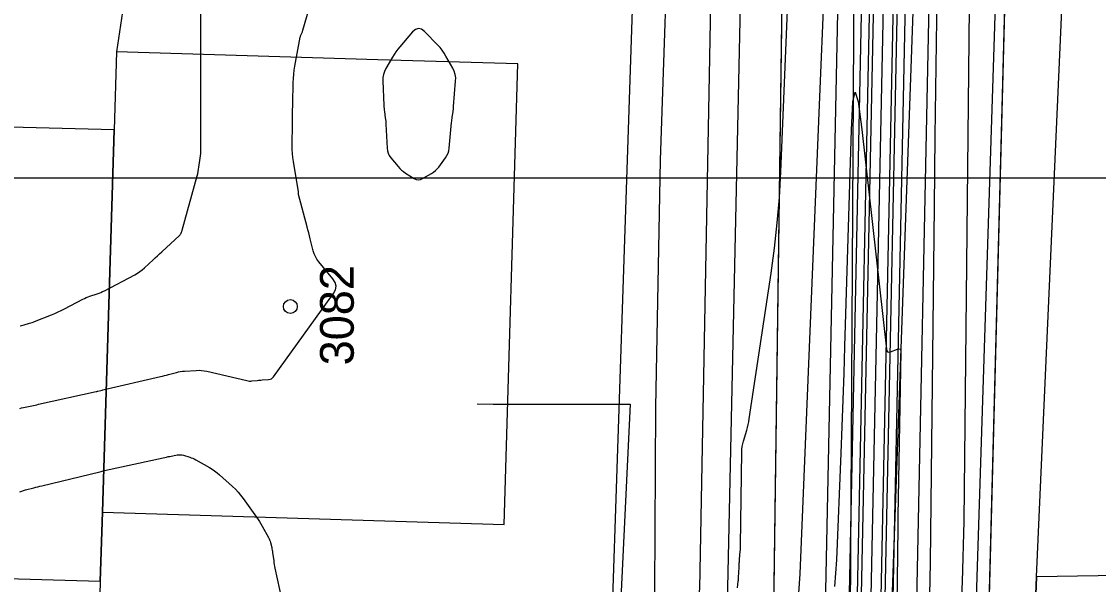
# Model space of a CAD drawing. Extents: x -534410 to -534262, y -1190162 to -1189584.
# Drawn here: x -534345.75 to -534318.59, y -1190119.71 to -1190105.52 of the extents above; entities that cross this region are included whole.
import ezdxf

# ---------------------------------------------------------------- set-up
doc = ezdxf.new("R2010")
doc.units = 0
for name, color, linetype in [('07_ELEKTRO', 7, 'Continuous'), ('30', 7, 'Continuous'), ('31', 7, 'Continuous'), ('_linie', 7, 'Continuous'), ('_N_osa', 7, 'Continuous'), ('_N_tenká', 7, 'Continuous'), ('_N_tenká_velmi', 7, 'Continuous'), ('_přístup', 7, 'Continuous'), ('_rámeček', 7, 'Continuous'), ('_tenka', 7, 'Continuous'), ('Default', 7, 'Continuous'), ('Hranice parcel', 7, 'Continuous'), ('Parcelní čísla', 7, 'Continuous'), ('Polygon budovy', 7, 'Continuous'), ('Vrstva 1', 7, 'Continuous'), ('Značky budov', 7, 'Continuous')]:
    doc.layers.add(name, color=color, linetype=linetype)

msp = doc.modelspace()

# ---------------------------------------------------------------- linework, layer by layer
at = {"layer": '07_ELEKTRO'}
msp.add_lwpolyline([(-534340.501, -1190135.539), (-534331.273, -1190133.27), (-534330.81, -1190133.08), (-534330.32, -1190132.66), (-534330.24, -1190132.17), (-534330.24, -1190130.93), (-534330.14, -1190126.19), (-534329.99, -1190122.81), (-534329.79, -1190121.43), (-534329.75, -1190115.24), (-534329.64, -1190109.01), (-534329.39, -1190101.86), (-534329.4, -1190094.43), (-534329.31, -1190087.46), (-534329.03, -1190079.95)], dxfattribs=at)
at = {"layer": '30'}
for points in [[(-534345.785, -1190115.274), (-534345.743, -1190115.262), (-534345.7, -1190115.252), (-534345.657, -1190115.243), (-534345.485, -1190115.206), (-534345.442, -1190115.197), (-534345.399, -1190115.188), (-534345.357, -1190115.179), (-534345.314, -1190115.169), (-534343.868, -1190114.85), (-534343.855, -1190114.847), (-534343.843, -1190114.844), (-534343.83, -1190114.841), (-534343.818, -1190114.838), (-534343.743, -1190114.818), (-534343.712, -1190114.81), (-534343.698, -1190114.807), (-534342.24, -1190114.471), (-534342.19, -1190114.459), (-534342.14, -1190114.447), (-534342.09, -1190114.434), (-534342.04, -1190114.42), (-534341.842, -1190114.365), (-534341.792, -1190114.352), (-534341.742, -1190114.342), (-534341.691, -1190114.335), (-534341.64, -1190114.331), (-534341.339, -1190114.313), (-534341.271, -1190114.311), (-534341.205, -1190114.315), (-534341.138, -1190114.323), (-534341.072, -1190114.336), (-534340.063, -1190114.572), (-534340.032, -1190114.578), (-534340, -1190114.582), (-534339.968, -1190114.582), (-534339.936, -1190114.58), (-534339.807, -1190114.566), (-534339.775, -1190114.562), (-534339.743, -1190114.559), (-534339.711, -1190114.557), (-534339.678, -1190114.555), (-534339.515, -1190114.545), (-534339.479, -1190114.539), (-534339.447, -1190114.526), (-534339.418, -1190114.506), (-534339.394, -1190114.478), (-534337.882, -1190112.378), (-534337.831, -1190112.282), (-534337.816, -1190112.187), (-534337.838, -1190112.094), (-534337.895, -1190112.002), (-534338.252, -1190111.575), (-534338.298, -1190111.512), (-534338.337, -1190111.446), (-534338.368, -1190111.376), (-534338.39, -1190111.302), (-534338.466, -1190110.997), (-534338.485, -1190110.921), (-534338.504, -1190110.845), (-534338.524, -1190110.769), (-534338.544, -1190110.693), (-534338.762, -1190109.876), (-534338.763, -1190109.871), (-534338.764, -1190109.866), (-534338.764, -1190109.861), (-534338.765, -1190109.856), (-534338.764, -1190109.834), (-534338.764, -1190109.829), (-534338.764, -1190109.824), (-534338.765, -1190109.819), (-534338.765, -1190109.813), (-534338.893, -1190109.05), (-534338.908, -1190108.947), (-534338.918, -1190108.844), (-534338.923, -1190108.74), (-534338.923, -1190108.636), (-534338.911, -1190108.094), (-534338.911, -1190108.053), (-534338.91, -1190108.011), (-534338.91, -1190107.969), (-534338.91, -1190107.928), (-534338.91, -1190107.761), (-534338.91, -1190107.72), (-534338.909, -1190107.678), (-534338.909, -1190107.636), (-534338.908, -1190107.595), (-534338.896, -1190107.053), (-534338.891, -1190106.949), (-534338.883, -1190106.845), (-534338.87, -1190106.742), (-534338.853, -1190106.64), (-534338.718, -1190105.907), (-534338.714, -1190105.891), (-534338.71, -1190105.876), (-534338.705, -1190105.862), (-534338.699, -1190105.847), (-534338.673, -1190105.79), (-534338.666, -1190105.775), (-534338.661, -1190105.761), (-534338.656, -1190105.746), (-534338.651, -1190105.731), (-534338.432, -1190104.986)], [(-534328.533, -1190137.603), (-534328.812, -1190134.889), (-534328.812, -1190134.881), (-534328.812, -1190134.873), (-534328.811, -1190134.866), (-534328.81, -1190134.858), (-534328.803, -1190134.826), (-534328.801, -1190134.819), (-534328.799, -1190134.811), (-534328.798, -1190134.803), (-534328.796, -1190134.795), (-534327.299, -1190125.114), (-534327.218, -1190124.637), (-534327.125, -1190124.162), (-534327.02, -1190123.691), (-534326.902, -1190123.222), (-534326.404, -1190121.352), (-534326.293, -1190120.882), (-534326.208, -1190120.408), (-534326.148, -1190119.931), (-534326.115, -1190119.449), (-534325.609, -1190107.213), (-534325.521, -1190105.013)], [(-534322.669, -1190104.87), (-534322.696, -1190106.64), (-534322.719, -1190108.41), (-534322.739, -1190110.18), (-534322.834, -1190119.161), (-534322.854, -1190119.98), (-534322.897, -1190120.797), (-534322.962, -1190121.613), (-534323.05, -1190122.427), (-534323.447, -1190125.682), (-534323.548, -1190126.496), (-534323.651, -1190127.309), (-534323.757, -1190128.122), (-534323.865, -1190128.934), (-534324.553, -1190134.018), (-534324.555, -1190134.032), (-534324.557, -1190134.046), (-534324.563, -1190134.074), (-534324.564, -1190134.082), (-534324.565, -1190134.089), (-534324.565, -1190134.096), (-534324.566, -1190134.103), (-534324.575, -1190136.191)]]:
    msp.add_lwpolyline(points, dxfattribs=at)
at = {"layer": '31'}
for points in [[(-534327.696, -1190119.802), (-534327.675, -1190119.627), (-534327.673, -1190119.603), (-534327.671, -1190119.579), (-534327.669, -1190119.556), (-534327.668, -1190119.532), (-534327.663, -1190119.411), (-534327.663, -1190119.4), (-534327.662, -1190119.389), (-534327.661, -1190119.378), (-534327.66, -1190119.367), (-534327.657, -1190119.323), (-534327.656, -1190119.313), (-534327.655, -1190119.302), (-534327.655, -1190119.291), (-534327.654, -1190119.28), (-534327.649, -1190119.164), (-534327.648, -1190119.141), (-534327.647, -1190119.118), (-534327.645, -1190119.095), (-534327.643, -1190119.072), (-534327.626, -1190118.882), (-534327.623, -1190118.843), (-534327.62, -1190118.803), (-534327.618, -1190118.764), (-534327.617, -1190118.724), (-534327.587, -1190116.379), (-534327.583, -1190116.308), (-534327.575, -1190116.237), (-534327.562, -1190116.167), (-534327.543, -1190116.097), (-534327.46, -1190115.821), (-534327.44, -1190115.752), (-534327.423, -1190115.682), (-534327.409, -1190115.611), (-534327.397, -1190115.54), (-534326.847, -1190111.866), (-534326.76, -1190111.229), (-534326.691, -1190110.59), (-534326.638, -1190109.95), (-534326.603, -1190109.308), (-534325.953, -1190093.609)], [(-534321.787, -1190098.669), (-534321.992, -1190118.118), (-534322.03, -1190119.643), (-534322.109, -1190121.165), (-534322.231, -1190122.685), (-534322.395, -1190124.201), (-534323.485, -1190133.139), (-534323.495, -1190133.215), (-534323.505, -1190133.292), (-534323.515, -1190133.368), (-534323.525, -1190133.445), (-534323.587, -1190133.902), (-534323.588, -1190133.909), (-534323.59, -1190134.29), (-534323.585, -1190134.352), (-534323.571, -1190134.41), (-534323.547, -1190134.466), (-534323.513, -1190134.518), (-534321.9, -1190136.637)], [(-534345.777, -1190113.189), (-534345.744, -1190113.183), (-534345.71, -1190113.176), (-534345.677, -1190113.167), (-534345.546, -1190113.127), (-534345.513, -1190113.117), (-534345.481, -1190113.106), (-534345.448, -1190113.094), (-534345.416, -1190113.082), (-534344.986, -1190112.91), (-534344.904, -1190112.876), (-534344.823, -1190112.84), (-534344.743, -1190112.802), (-534344.664, -1190112.762), (-534344.2, -1190112.519), (-534344.157, -1190112.497), (-534344.112, -1190112.477), (-534344.067, -1190112.459), (-534344.021, -1190112.443), (-534343.836, -1190112.382), (-534343.79, -1190112.366), (-534343.745, -1190112.348), (-534343.7, -1190112.328), (-534343.657, -1190112.306), (-534342.888, -1190111.901), (-534342.824, -1190111.864), (-534342.762, -1190111.823), (-534342.704, -1190111.778), (-534342.648, -1190111.729), (-534342.43, -1190111.525), (-534342.376, -1190111.474), (-534342.321, -1190111.423), (-534342.266, -1190111.372), (-534342.211, -1190111.322), (-534341.762, -1190110.91), (-534341.753, -1190110.901), (-534341.745, -1190110.892), (-534341.738, -1190110.881), (-534341.733, -1190110.87), (-534341.712, -1190110.825), (-534341.707, -1190110.814), (-534341.702, -1190110.802), (-534341.698, -1190110.79), (-534341.694, -1190110.778), (-534341.318, -1190109.411), (-534341.303, -1190109.356), (-534341.291, -1190109.3), (-534341.28, -1190109.243), (-534341.272, -1190109.186), (-534341.241, -1190108.958), (-534341.234, -1190108.901), (-534341.229, -1190108.844), (-534341.226, -1190108.787), (-534341.225, -1190108.729), (-534341.225, -1190104.959)], [(-534325.239, -1190119.765), (-534325.193, -1190119.095), (-534325.082, -1190116.405), (-534325.055, -1190115.733), (-534325.03, -1190115.061), (-534325.007, -1190114.388), (-534324.986, -1190113.715), (-534324.823, -1190108.248), (-534324.785, -1190107.538), (-534324.729, -1190107.299), (-534324.653, -1190107.532), (-534324.558, -1190108.237), (-534323.942, -1190113.783), (-534323.932, -1190113.823), (-534323.912, -1190113.846), (-534323.882, -1190113.853), (-534323.842, -1190113.845), (-534323.664, -1190113.78), (-534323.625, -1190113.772), (-534323.597, -1190113.779), (-534323.581, -1190113.803), (-534323.576, -1190113.842), (-534323.649, -1190117.988), (-534323.653, -1190118.232), (-534323.656, -1190118.476), (-534323.66, -1190118.72), (-534323.662, -1190118.964), (-534323.675, -1190120.203)], [(-534345.791, -1190117.376), (-534345.742, -1190117.358), (-534345.692, -1190117.343), (-534345.642, -1190117.329), (-534345.439, -1190117.276), (-534345.388, -1190117.263), (-534345.338, -1190117.25), (-534345.287, -1190117.238), (-534345.236, -1190117.225), (-534343.774, -1190116.871), (-534343.737, -1190116.862), (-534343.689, -1190116.849), (-534343.671, -1190116.845), (-534343.653, -1190116.841), (-534342.175, -1190116.517), (-534342.132, -1190116.508), (-534342.089, -1190116.499), (-534342.046, -1190116.49), (-534342.003, -1190116.482), (-534341.824, -1190116.447), (-534341.784, -1190116.441), (-534341.744, -1190116.441), (-534341.704, -1190116.445), (-534341.664, -1190116.455), (-534341.505, -1190116.503), (-534341.466, -1190116.516), (-534341.428, -1190116.531), (-534341.39, -1190116.549), (-534341.354, -1190116.568), (-534341.01, -1190116.765), (-534340.942, -1190116.807), (-534340.877, -1190116.851), (-534340.814, -1190116.9), (-534340.753, -1190116.951), (-534340.426, -1190117.245), (-534340.354, -1190117.314), (-534340.286, -1190117.386), (-534340.222, -1190117.462), (-534340.161, -1190117.542), (-534339.82, -1190118.02), (-534339.782, -1190118.074), (-534339.746, -1190118.129), (-534339.712, -1190118.185), (-534339.679, -1190118.242), (-534339.519, -1190118.53), (-534339.504, -1190118.56), (-534339.491, -1190118.59), (-534339.48, -1190118.621), (-534339.471, -1190118.652), (-534339.439, -1190118.78), (-534339.432, -1190118.813), (-534339.425, -1190118.845), (-534339.42, -1190118.877), (-534339.415, -1190118.91), (-534339.387, -1190119.12), (-534339.381, -1190119.166), (-534339.373, -1190119.212), (-534339.365, -1190119.258), (-534339.356, -1190119.303), (-534339.184, -1190120.11)]]:
    msp.add_lwpolyline(points, dxfattribs=at)
msp.add_lwpolyline([(-534336.568, -1190107.986), (-534336.564, -1190108.026), (-534336.561, -1190108.065), (-534336.558, -1190108.105), (-534336.529, -1190108.706), (-534336.521, -1190108.773), (-534336.502, -1190108.837), (-534336.473, -1190108.896), (-534336.434, -1190108.951), (-534336.25, -1190109.174), (-534336.208, -1190109.221), (-534336.163, -1190109.264), (-534336.115, -1190109.302), (-534336.063, -1190109.338), (-534335.85, -1190109.471), (-534335.796, -1190109.496), (-534335.742, -1190109.505), (-534335.688, -1190109.498), (-534335.634, -1190109.475), (-534335.411, -1190109.35), (-534335.358, -1190109.316), (-534335.309, -1190109.277), (-534335.265, -1190109.234), (-534335.225, -1190109.185), (-534335.055, -1190108.955), (-534335.019, -1190108.898), (-534334.991, -1190108.838), (-534334.971, -1190108.774), (-534334.961, -1190108.707), (-534334.903, -1190108.066), (-534334.9, -1190108.032), (-534334.896, -1190107.998), (-534334.892, -1190107.965), (-534334.887, -1190107.931), (-534334.867, -1190107.797), (-534334.862, -1190107.764), (-534334.858, -1190107.73), (-534334.855, -1190107.697), (-534334.852, -1190107.663), (-534334.801, -1190107.02), (-534334.8, -1190106.933), (-534334.812, -1190106.85), (-534334.836, -1190106.769), (-534334.873, -1190106.692), (-534335.045, -1190106.386), (-534335.09, -1190106.311), (-534335.14, -1190106.24), (-534335.195, -1190106.172), (-534335.254, -1190106.108), (-534335.59, -1190105.767), (-534335.666, -1190105.709), (-534335.74, -1190105.692), (-534335.813, -1190105.714), (-534335.885, -1190105.777), (-534336.205, -1190106.151), (-534336.257, -1190106.214), (-534336.306, -1190106.28), (-534336.352, -1190106.348), (-534336.395, -1190106.418), (-534336.56, -1190106.702), (-534336.595, -1190106.775), (-534336.62, -1190106.85), (-534336.633, -1190106.928), (-534336.636, -1190107.009), (-534336.611, -1190107.63), (-534336.609, -1190107.669), (-534336.606, -1190107.709), (-534336.602, -1190107.749), (-534336.596, -1190107.788), (-534336.574, -1190107.946)], close=True, dxfattribs=at)
at = {"layer": '_linie'}
for points in [[(-534351.8, -1189951.99), (-534346.88, -1189964.25), (-534328.11, -1190005.55), (-534325.796, -1190021.686), (-534325.86, -1190050.97), (-534326.22, -1190078.56), (-534326.79, -1190120.4), (-534329.12, -1190134.93), (-534323.49, -1190133.89), (-534321.38, -1190121.46), (-534319.59, -1190053.22), (-534320.45, -1190021.195), (-534322.75, -1190003.33), (-534340.65, -1189960.04), (-534344.52, -1189948.89)], [(-534347.45, -1189950.137), (-534345.54, -1189954.54), (-534325.02, -1190005.35), (-534322.054, -1190021.393), (-534321.72, -1190051.56), (-534322.31, -1190078.15), (-534323.81, -1190120.37), (-534326.521, -1190134.45)], [(-534328.194, -1190134.759), (-534324.85, -1190120.45), (-534324.6, -1190078.17), (-534323.54, -1190051.92), (-534323.273, -1190021.516), (-534325.81, -1190005.43), (-534346.66, -1189954.59), (-534348.342, -1189950.518)]]:
    msp.add_lwpolyline(points, dxfattribs=at)
at = {"layer": '_N_osa'}
msp.add_lwpolyline([(-534327.357, -1190134.604), (-534324.33, -1190120.41), (-534323.455, -1190078.16), (-534322.63, -1190051.74), (-534322.663, -1190021.455), (-534325.415, -1190005.39), (-534346.1, -1189954.565), (-534347.892, -1189950.326)], dxfattribs=at)
at = {"layer": '_N_tenká'}
for points in [[(-534326.133, -1190134.378), (-534323.183, -1190120.543), (-534322.305, -1190078.19), (-534321.48, -1190051.757), (-534321.513, -1190021.356), (-534324.303, -1190005.072), (-534345.038, -1189954.124), (-534346.832, -1189949.878)], [(-534327.091, -1190134.555), (-534324.081, -1190120.439), (-534323.205, -1190078.166), (-534322.38, -1190051.744), (-534322.413, -1190021.433), (-534325.173, -1190005.321), (-534345.869, -1189954.469), (-534347.661, -1189950.228)], [(-534327.623, -1190134.654), (-534324.579, -1190120.381), (-534323.705, -1190078.154), (-534322.88, -1190051.736), (-534322.913, -1190021.476), (-534325.657, -1190005.459), (-534346.331, -1189954.661), (-534348.122, -1189950.423)], [(-534328.581, -1190134.83), (-534325.477, -1190120.277), (-534324.605, -1190078.13), (-534323.78, -1190051.723), (-534323.813, -1190021.553), (-534326.527, -1190005.708), (-534347.162, -1189955.006), (-534348.951, -1189950.773)]]:
    msp.add_lwpolyline(points, dxfattribs=at)
at = {"layer": '_N_tenká_velmi'}
for points in [[(-534326.985, -1190134.536), (-534323.981, -1190120.45), (-534323.105, -1190078.169), (-534322.28, -1190051.745), (-534322.313, -1190021.425), (-534325.076, -1190005.293), (-534345.777, -1189954.431), (-534347.569, -1189950.189)], [(-534326.772, -1190134.496), (-534323.781, -1190120.474), (-534322.905, -1190078.174), (-534322.08, -1190051.748), (-534322.113, -1190021.407), (-534324.883, -1190005.238), (-534345.592, -1189954.354), (-534347.385, -1189950.112)], [(-534327.73, -1190134.673), (-534324.679, -1190120.37), (-534323.805, -1190078.151), (-534322.98, -1190051.735), (-534323.013, -1190021.485), (-534325.754, -1190005.487), (-534346.423, -1189954.699), (-534348.214, -1189950.462)], [(-534327.943, -1190134.713), (-534324.879, -1190120.346), (-534324.005, -1190078.146), (-534323.18, -1190051.732), (-534323.213, -1190021.502), (-534325.947, -1190005.542), (-534346.608, -1189954.776), (-534348.398, -1189950.54)]]:
    msp.add_lwpolyline(points, dxfattribs=at)
at = {"layer": '_přístup'}
msp.add_lwpolyline([(-534330.552, -1190135.191), (-534328.648, -1190119.819), (-534326.845, -1190024.247), (-534332.805, -1189999.297), (-534354.454, -1189948.317)], dxfattribs=at)
at = {"layer": '_rámeček'}
msp.add_lwpolyline([(-534410.126, -1190004.47), (-534261.626, -1190004.47), (-534261.626, -1190109.47), (-534410.126, -1190109.47)], close=True, dxfattribs=at)
at = {"layer": '_tenka'}
for points in [[(-534351.8, -1189951.99), (-534346.88, -1189964.25), (-534328.11, -1190005.55), (-534325.796, -1190021.686), (-534325.86, -1190050.97), (-534326.22, -1190078.56), (-534326.79, -1190120.4), (-534329.12, -1190134.93), (-534323.49, -1190133.89), (-534321.38, -1190121.46), (-534319.59, -1190053.22), (-534320.45, -1190021.195), (-534322.75, -1190003.33), (-534340.65, -1189960.04), (-534344.52, -1189948.89)], [(-534327.55, -1190134.64), (-534323.49, -1190133.89), (-534321.38, -1190121.46), (-534319.59, -1190053.22), (-534320.45, -1190021.195), (-534322.75, -1190003.33), (-534340.65, -1189960.04), (-534344.52, -1189948.89)], [(-534347.45, -1189950.137), (-534345.54, -1189954.54), (-534325.02, -1190005.35), (-534322.054, -1190021.393), (-534321.72, -1190051.56), (-534322.31, -1190078.15), (-534323.81, -1190120.37), (-534326.521, -1190134.45)], [(-534347.45, -1189950.137), (-534345.54, -1189954.54), (-534325.02, -1190005.35), (-534322.054, -1190021.393), (-534321.72, -1190051.56), (-534322.31, -1190078.15), (-534323.81, -1190120.37), (-534326.521, -1190134.45)], [(-534328.194, -1190134.759), (-534324.85, -1190120.45), (-534324.6, -1190078.17), (-534323.54, -1190051.92), (-534323.273, -1190021.516), (-534325.81, -1190005.43), (-534346.66, -1189954.59), (-534348.342, -1189950.518)], [(-534328.194, -1190134.759), (-534324.85, -1190120.45), (-534324.6, -1190078.17), (-534323.54, -1190051.92), (-534323.273, -1190021.516), (-534325.81, -1190005.43), (-534346.66, -1189954.59), (-534348.342, -1189950.518)], [(-534351.8, -1189951.99), (-534346.88, -1189964.25), (-534328.11, -1190005.55), (-534325.796, -1190021.686), (-534325.86, -1190050.97), (-534326.22, -1190078.56), (-534326.79, -1190120.4), (-534329.12, -1190134.93), (-534327.55, -1190134.64)]]:
    msp.add_lwpolyline(points, dxfattribs=at)
at = {"layer": 'Default'}
for p, q in [((-534321.38, -1190121.46), (-534319.59, -1190053.22)), ((-534326.22, -1190078.56), (-534326.79, -1190120.4))]:
    msp.add_line(p, q, dxfattribs=at)
at = {"layer": 'Hranice parcel'}
msp.add_line((-534343.76, -1190119.63), (-534344.25, -1190135.21), dxfattribs=at)
for points in [[(-534333.99, -1189993.03), (-534331.98, -1189997.67), (-534327.34, -1190013.08), (-534325.48, -1190021.81), (-534326.93, -1190073), (-534328.13, -1190128.3), (-534328.71, -1190131.86)], [(-534322.11, -1190134.26), (-534321.95, -1190128.7), (-534320.16, -1190072.85), (-534318.8, -1190033.53)], [(-534320.3, -1190128.29), (-534320.41, -1190126.09), (-534320.16, -1190119.52), (-534319.24, -1190099.01), (-534318.88, -1190092.72), (-534318.39, -1190085.1)], [(-534331.23, -1190131.88), (-534330.53, -1190110.76), (-534329.74, -1190087.07)], [(-534342.85, -1190101.1), (-534342.97, -1190103.75), (-534343.35, -1190106.28), (-534343.41, -1190108.25)], [(-534343.41, -1190108.25), (-534357.86, -1190107.88), (-534357.95, -1190110.98), (-534359.56, -1190112.38), (-534359.55, -1190114.54), (-534358.11, -1190116.13), (-534358.2, -1190119.22), (-534343.76, -1190119.63)], [(-534343.41, -1190108.25), (-534343.7, -1190117.89), (-534343.76, -1190119.63)]]:
    msp.add_lwpolyline(points, dxfattribs=at)
at = {"layer": 'Polygon budovy'}
for points in [[(-534336.76, -1190106.48), (-534343.35, -1190106.28), (-534343.41, -1190108.25), (-534343.7, -1190117.89), (-534333.58, -1190118.2), (-534333.23, -1190106.58)], [(-534343.7, -1190117.89), (-534343.41, -1190108.25), (-534357.86, -1190107.88), (-534357.95, -1190110.98), (-534359.56, -1190112.38), (-534359.55, -1190114.54), (-534358.11, -1190116.13), (-534358.2, -1190119.22), (-534343.76, -1190119.63)], [(-534310.83, -1190119.37), (-534320.16, -1190119.52), (-534320.41, -1190126.09), (-534310.57, -1190125.63)]]:
    msp.add_lwpolyline(points, close=True, dxfattribs=at)
at = {"layer": 'Vrstva 1'}
msp.add_lwpolyline([(-534334.258, -1190115.158), (-534333.859, -1190115.17), (-534330.4, -1190115.17), (-534331.19, -1190131.62)], dxfattribs=at)
at = {"layer": 'Značky budov'}
msp.add_circle((-534338.968, -1190112.705), 0.175, dxfattribs=at)

# ---------------------------------------------------------------- texts
at = {"layer": 'Parcelní čísla'}
msp.add_text('3082', height=0.85, rotation=90, dxfattribs=at).set_placement((-534337.37, -1190114.187))

doc.saveas('drawing.dxf')
